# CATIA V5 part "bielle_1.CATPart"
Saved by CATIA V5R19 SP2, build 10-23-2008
Part number: bielle_1
Bounding box of the stored display mesh (mm): x -10 to 20, y -7.997 to 7.997, z -7.99 to 77.99
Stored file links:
  D:\Dropbox\IAO_2011\MMS_GR2\IAO_2011_1492_afeiguel\IAO_2011_1492_afeiguel\bielle_1.CATPart
  C:\Users\Nono\Desktop\projets ifma\IAO finis\assemblage_IAO.CATProduct
  D:\Dropbox\IAO_2011\MMS_GR2\IAO_2011_1492_afeiguel\IAO_2011_1492_afeiguel\bielle_2.CATPart
  D:\Dropbox\IAO_2011\MMS_GR2\IAO_2011_1492_afeiguel\IAO_2011_1492_afeiguel\bati_0.CATPart
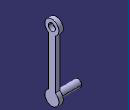
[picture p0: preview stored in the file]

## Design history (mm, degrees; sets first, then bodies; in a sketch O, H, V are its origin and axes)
Parameters
  AB = 70 mm
External parameters (linked from other documents)
  External.r_tetebielle = 8 mm
  `External.épaisseur` = 20 mm
  External.e_bielle = 5 mm
Set1
  DatumSurface1: linked copy from another document
  DatumPoint1: linked copy from another document
  DatumSurface2: linked copy from another document
Body1 (main body)
  Sketch1 on yz-plane, origin (0, 0, 0), H (0, 1, 0), V (0, 0, 1)
    point P1 (0, 0)
    point P2 (0, 70)
    line L1 (0, 0) -> (0, 70)
    distance P2 O = 70 {= AB}
    coincidence: P1 O, P2 V
    vertical: L1 V
  Sketch2 on zx-plane, origin (0, 0, 0), H (-1, 0, 0), V (0, 0, 1)
    line L1 (-49.8432, 0) -> (44.8141, 0)
    point P1 (-49.8432, 0)
    line L2 (-49.8432, 70) -> (44.8141, 70)
    reference projected point E1 (0, 70) from Sketch1.P2
    distance L2 E1 = 0
    coincidence: P1 H
    horizontal: L1 H, L2 H
  Plane1: type Offset, RefPlane yz-plane, Offset 15 {= External.e_bielle  +`External.épaisseur` /2}
  Sketch3 on Plane1, origin (15, 0, 0), H (0, 1, 0), V (0, 0, 1)
    circle A1 centre (3.7585, 69.2833) radius 0.1738
    arc A2 centre (0, 0) radius 8 from (-3.873, 7) to (3.873, 7) ccw
    point P3 (-3.873, 7)
    point P4 (3.873, 7)
    point P5 (4, 0)
    line L1 (3.873, 63) -> (3.873, 7)
    arc A3 centre (0, 70) radius 8 from (3.873, 63) to (-3.873, 63) ccw
    point P6 (0, 70)
    line L2 (-3.873, 63) -> (-3.873, 7)
    circle A4 centre (0, 70) radius 4
    reference projected point E1 (0, 70) from Sketch1.P2
    distance H P3 = 7 {= External.r_tetebielle -1mm}
    distance P4 H = 7 {= External.r_tetebielle -1mm}
    radius A4 = 4 {= External.r_tetebielle -4mm}
    radius A3 = 8 {= External.r_tetebielle}
    coincidence: P5 H, E1 P6
    tangency: A4 A1
  Pad1: profile Sketch3, direction (1, 0, 0), length 5
  Sketch4 on start face of Pad1, origin (15, 0, 0), H (0, -1, 0), V (0, 0, 1)
    circle A1 centre (0, 0) radius 4
    reference projected point E1 (0, 0) from vertex of DatumPoint1
    distance A1 E1 = 4 {= External.r_tetebielle -4mm}
  Pad2: profile Sketch4, direction (-1, 0, 0), length 25 {= `External.épaisseur` +External.e_bielle}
